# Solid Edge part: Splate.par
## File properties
Title: Side Plate
Subject: Carrier Assembly
Author: kiyo
Keywords: Side Plate
Comments: Side Plate
Template: metric.par
Last saved by: edge
Revision: 36
Application: Solid Edge
File Size: 0
Number of Sheets: 0
Number of Objects: 0
Username: kiyo
文書内容のタイプ: 0
Material: Steel
Face Style: Steel
Fill Style: ANSI32(Steel)
Virtual Style: Machined steel
Coef. of Thermal Exp: 1.3e-05
Thermal Conductivity: 32.0
Specific Heat: 481.0
Modulus of Elasticity: 199947953000.0
Poisson's Ratio: 0.29
Yield Stress: 262000766.0
Ultimate Stress: 358527364.0
Elongation: 0.0
Category: Machined Plate
Manager: Brian Little
Company: Wheels R Us
Density: 0.28298507824 lbm/in^3
Accuracy: 0.00
てすと: てすと
Document Number: SP-2070
Revision: 1
Project Name: Trolley Wheel Assembly
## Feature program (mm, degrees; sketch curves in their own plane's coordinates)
sketch for "unnamed Protrusion 1" plane through (0, 0, 0) normal (0, -1, 0) x-axis (1, 0, 0)
  line (-41.3956, 47.354) -> (78.6044, 47.354)
  line (78.6044, 47.354) -> (78.6044, -2.646)
  line (78.6044, -2.646) -> (43.6044, -132.646)
  line (43.6044, -132.646) -> (-6.3956, -132.646)
  line (-41.3956, -2.646) -> (-6.3956, -132.646)
  line (-41.3956, 47.354) -> (-41.3956, -2.646)
extrude "unnamed Protrusion 1" add finite 15 along -normal
sketch for "unnamed Hole 1" plane through (18.6044, 0, -42.646) normal (0, -1, 0) x-axis (1, 0, 0)
  hole centre (0, -60) bore radius 15
hole "unnamed Hole 1" through
sketch for "Hole_2" plane through (18.6044, 0, -42.646) normal (0, -1, 0) x-axis (1, 0, 0)
  hole centre (30, 65) bore radius 10
hole "Hole_2" through
sketch for "Hole_3" plane through (18.6044, 0, -42.646) normal (0, -1, 0) x-axis (1, 0, 0)
  hole centre (-30, 65) bore radius 10
hole "Hole_3" through
pattern "unnamed Pattern 1" of "Hole_2", "Hole_3"
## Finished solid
Body 1: solid body, 11 faces, 24 edges, 12 vertices.
  Faces by surface: plane 8, cylinder 3
  Edges by curve: line 18, circle 6
Bounding box of the edges (mm): 120.000 x 15.000 x 180.000, from (-41.3956, 0, -132.646) to (78.6044, 15, 47.354).
Cylindrical faces by radius (mm): R10 x2, R15 x1
Planar faces by outward normal: +x 1, +y 1, +z 1, -x 1, -y 1, -z 1, oblique 2
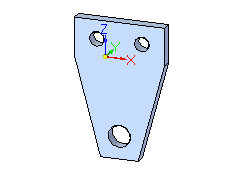
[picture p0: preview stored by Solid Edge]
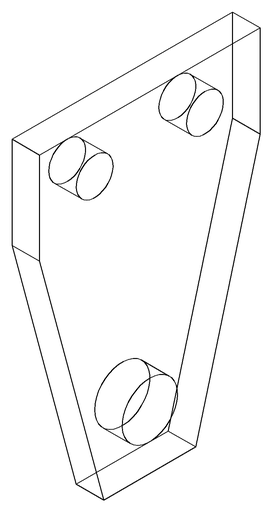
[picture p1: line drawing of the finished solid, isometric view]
